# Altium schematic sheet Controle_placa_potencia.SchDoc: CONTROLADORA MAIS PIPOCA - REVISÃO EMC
size A3; DocumentNumber: GA0050; SheetNumber: 8; SheetTotal: 17
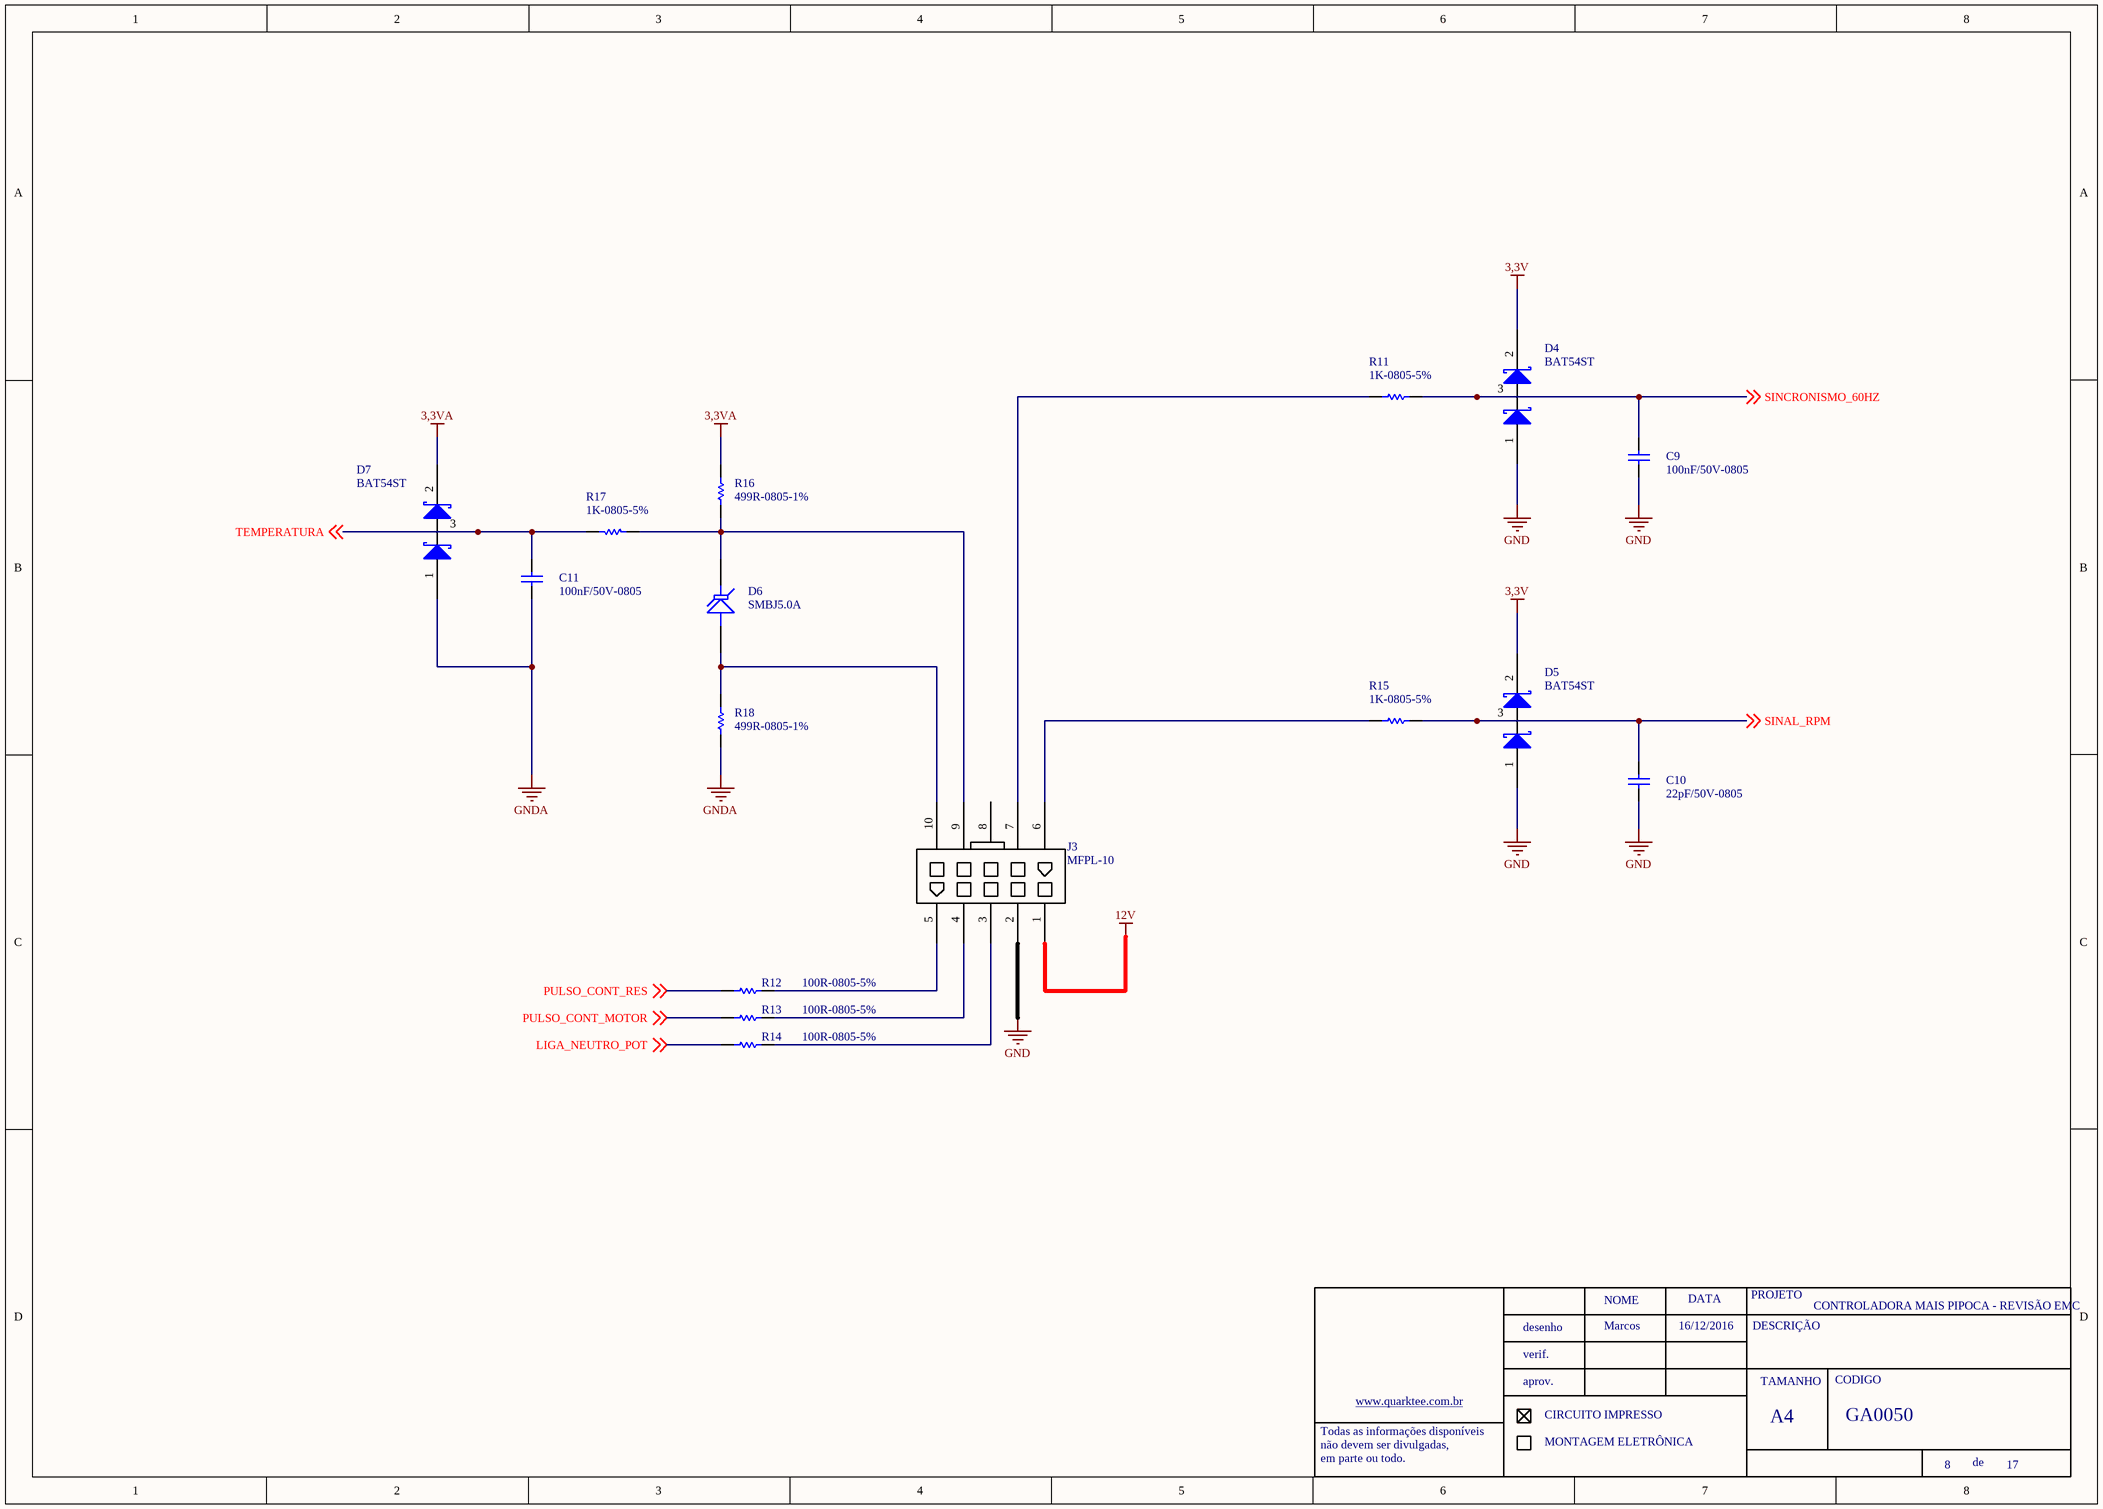
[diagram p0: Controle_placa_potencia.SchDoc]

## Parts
C9  100nF/50V-0805  [0805-REVISADO ONDA]
C10  22pF/50V-0805  [0805-REVISADO ONDA]
C11  100nF/50V-0805  [0805-REVISADO ONDA]
D4  BAT54ST  [SOT23 - REVISADO ONDA]
D5  BAT54ST  [SOT23 - REVISADO ONDA]
D6  SMBJ5.0A  [SMA DIODES]
D7  BAT54ST  [SOT23 - REVISADO ONDA]
J3  MFPL-10
R11  1K-0805-5%  [0805-REVISADO ONDA]
R12  100R-0805-5%  [0805-REVISADO ONDA]
R13  100R-0805-5%  [0805-REVISADO ONDA]
R14  100R-0805-5%  [0805-REVISADO ONDA]
R15  1K-0805-5%  [0805-REVISADO ONDA]
R16  499R-0805-1%  [0805-REVISADO ONDA]
R17  1K-0805-5%  [0805-REVISADO ONDA]
R18  499R-0805-1%  [0805-REVISADO ONDA]

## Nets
3,3V: D4.2 D5.2
3,3VA: D7.2 R16.2
12V: J3.1
GND: C9.2 C10.2 D4.1 D5.1 J3.2
GNDA: C11.1 D7.1 R18.1
LIGA_NEUTRO_POT: R14.1 ; off-sheet LIGA_NEUTRO_POT
PULSO_CONT_MOTOR: R13.1 ; off-sheet PULSO_CONT_MOTOR
PULSO_CONT_RES: R12.2 ; off-sheet PULSO_CONT_RES
SINAL_RPM: C10.1 D5.3 R15.2 ; off-sheet SINAL_RPM
SINCRONISMO_60HZ: C9.1 D4.3 R11.2 ; off-sheet SINCRONISMO_60HZ
TEMPERATURA: C11.2 D7.3 R17.2 ; off-sheet TEMPERATURA
NetD6_1: D6.1(A) J3.10 R18.2
NetD6_2: D6.2(K) J3.9 R16.1 R17.1
NetJ3_3: J3.3 R14.2
NetJ3_4: J3.4 R13.2
NetJ3_5: J3.5 R12.1
NetJ3_6: J3.6 R15.1
NetJ3_7: J3.7 R11.1

Not connected (* = marked no-connect by the designer): J3 8

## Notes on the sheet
- Marcos
- 16/12/2016

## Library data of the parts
C9 C11 = 100nF/50-0805-NPO
C10 = 100nF/50-0805-NPO: 100nF/50V-0805
R16 R18 = 10K-0805-5%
